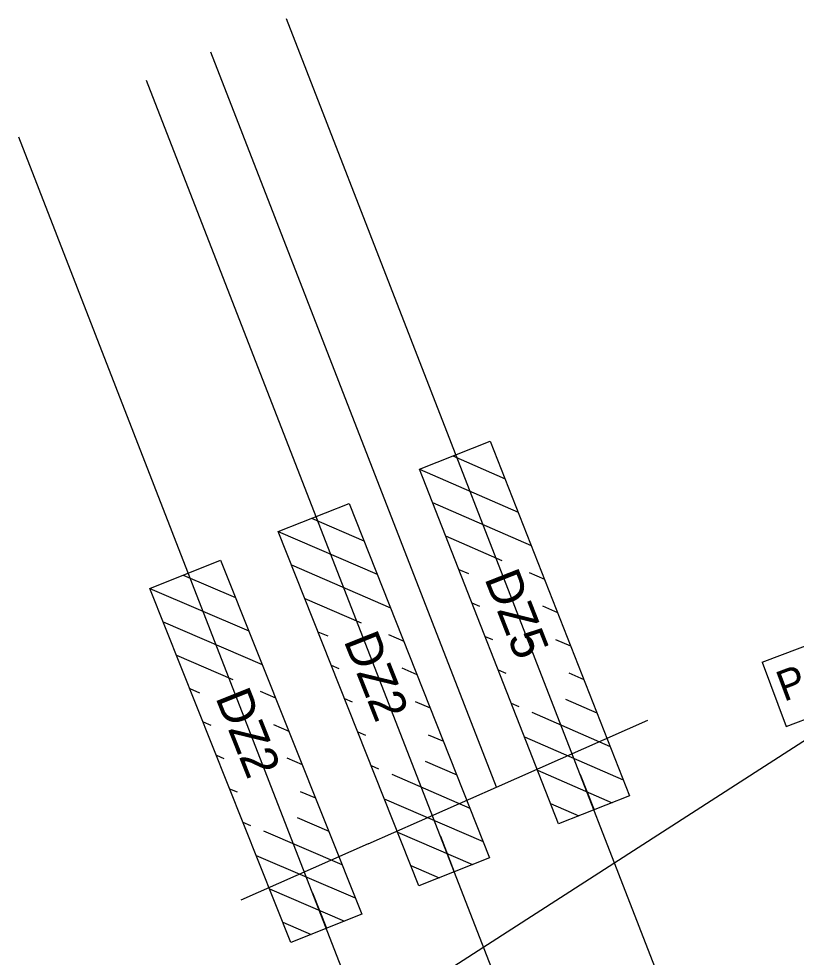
# Model space of a CAD drawing. Extents: x 510435 to 510719, y 1315254 to 1315553.
# Drawn here: x 510505.5 to 510566.7, y 1315479.2 to 1315553.1 of the extents above; entities that cross this region are included whole.
import ezdxf

# ---------------------------------------------------------------- set-up
doc = ezdxf.new("R2010")
doc.units = 0
for name, color, linetype in [('ConduitDB', 7, 'Continuous'), ('Default', 7, 'Continuous'), ('NonPlottingEle_dp', 7, 'Continuous'), ('OverheadStr', 7, 'Continuous'), ('PedHead', 7, 'Continuous')]:
    doc.layers.add(name, color=color, linetype=linetype)

# ---------------------------------------------------------------- blocks, each defined once
blk = doc.blocks.new('MastArmD4')
at = {"layer": 'OverheadStr'}
for p, q in [((0.25, 1.5), (0, 1.5)), ((0, 1.5), (0, -1.5)), ((0.25, 1.5), (0.25, -1.5)), ((0, -1.042), (0, 1.042)), ((0.25, 0.582), (11.7, 0.515)), ((9.7, 0.542), (46, 0.33)), ((9.7, 0.542), (9.7, -0.542)), ((11.7, 0.515), (11.7, -0.515)), ((46, 0.33), (46, -0.33)), ((0.25, -0.582), (11.7, -0.515)), ((9.7, -0.542), (46, -0.33)), ((0.25, -1.5), (0, -1.5))]:
    blk.add_line(p, q, dxfattribs=at)

msp = doc.modelspace()

# ---------------------------------------------------------------- linework, layer by layer
at = {"layer": 'ConduitDB'}
msp.add_line((510521.957, 1315467.05), (510573.336, 1315500.096), dxfattribs=at)
at = {"layer": 'Default'}
for p, q in [((510539.679, 1315518.645), (510543.79, 1315516.852)), ((510537.046, 1315517.611), (510544.824, 1315514.219)), ((510538.08, 1315514.979), (510545.857, 1315511.586)), ((510528.558, 1315513.735), (510532.677, 1315511.958)), ((510525.93, 1315512.691), (510533.721, 1315509.329)), ((510539.113, 1315512.346), (510543.543, 1315510.413)), ((510526.974, 1315510.062), (510534.765, 1315506.701)), ((510540.147, 1315509.713), (510540.91, 1315509.38)), ((510518.445, 1315509.267), (510522.566, 1315507.496)), ((510545.701, 1315509.472), (510546.891, 1315508.953)), ((510515.818, 1315508.219), (510523.614, 1315504.869)), ((510528.018, 1315507.433), (510532.455, 1315505.519)), ((510541.18, 1315507.08), (510541.779, 1315506.819)), ((510546.735, 1315506.839), (510547.924, 1315506.32)), ((510516.866, 1315505.592), (510524.662, 1315502.242)), ((510529.062, 1315504.805), (510529.826, 1315504.475)), ((510534.617, 1315504.586), (510535.809, 1315504.072)), ((510542.214, 1315504.447), (510542.813, 1315504.186)), ((510547.768, 1315504.206), (510548.958, 1315503.687)), ((510517.914, 1315502.965), (510522.354, 1315501.057)), ((510530.106, 1315502.176), (510530.706, 1315501.917)), ((510535.661, 1315501.957), (510536.853, 1315501.443)), ((510543.247, 1315501.814), (510543.846, 1315501.553)), ((510548.802, 1315501.574), (510549.991, 1315501.055)), ((510518.962, 1315500.338), (510519.727, 1315500.009)), ((510524.517, 1315500.128), (510525.71, 1315499.615)), ((510531.15, 1315499.547), (510531.75, 1315499.288)), ((510536.705, 1315499.329), (510537.897, 1315498.815)), ((510548.539, 1315499.506), (510551.025, 1315498.422)), ((510544.281, 1315499.182), (510544.88, 1315498.92)), ((510545.907, 1315498.472), (510552.058, 1315495.789)), ((510520.01, 1315497.71), (510520.611, 1315497.452)), ((510525.566, 1315497.5), (510526.758, 1315496.988)), ((510532.194, 1315496.919), (510532.794, 1315496.66)), ((510537.749, 1315496.7), (510538.941, 1315496.186)), ((510545.314, 1315496.549), (510553.092, 1315493.156)), ((510521.058, 1315495.083), (510521.659, 1315494.825)), ((510526.614, 1315494.873), (510527.806, 1315494.361)), ((510533.238, 1315494.29), (510533.838, 1315494.031)), ((510537.495, 1315494.631), (510539.985, 1315493.557)), ((510534.867, 1315493.587), (510541.029, 1315490.928)), ((510546.348, 1315493.916), (510552.235, 1315491.348)), ((510522.106, 1315492.456), (510522.707, 1315492.198)), ((510527.662, 1315492.246), (510528.854, 1315491.734)), ((510534.282, 1315491.661), (510542.073, 1315488.3)), ((510547.382, 1315491.283), (510549.602, 1315490.314)), ((510523.154, 1315489.829), (510523.755, 1315489.571)), ((510527.411, 1315490.177), (510529.903, 1315489.107)), ((510524.784, 1315489.129), (510530.951, 1315486.48)), ((510535.326, 1315489.033), (510541.224, 1315486.488)), ((510524.203, 1315487.202), (510531.999, 1315483.853)), ((510536.37, 1315486.404), (510538.595, 1315485.444)), ((510525.251, 1315484.575), (510531.152, 1315482.04)), ((510526.299, 1315481.948), (510528.525, 1315480.992))]:
    msp.add_line(p, q, dxfattribs=at)
for points in [[(510542.631, 1315519.804), (510553.593, 1315491.881), (510548.008, 1315489.688), (510537.046, 1315517.611)], [(510531.506, 1315514.906), (510542.579, 1315487.026), (510537.003, 1315484.812), (510525.93, 1315512.691)], [(510521.39, 1315510.442), (510532.506, 1315482.58), (510526.934, 1315480.357), (510515.818, 1315508.219)]]:
    msp.add_lwpolyline(points, close=True, dxfattribs=at)
at = {"layer": 'NonPlottingEle_dp'}
for p, q in [((510565.341, 1315453.401), (510526.579, 1315553.053)), ((510543.121, 1315492.582), (510520.623, 1315550.421)), ((510560.844, 1315431.795), (510515.57, 1315548.188)), ((510556.729, 1315412.031), (510505.499, 1315543.737)), ((510543.121, 1315492.582), (510555.033, 1315497.847)), ((510543.121, 1315492.582), (510555.033, 1315497.847)), ((510549.713, 1315493.58), (510550.8, 1315490.784)), ((510533.014, 1315488.116), (510543.121, 1315492.582)), ((510538.703, 1315488.715), (510539.791, 1315485.919)), ((510533.014, 1315488.116), (510522.98, 1315483.681)), ((510528.633, 1315484.264), (510529.358, 1315482.4)), ((510528.633, 1315484.264), (510529.72, 1315481.468))]:
    msp.add_line(p, q, dxfattribs=at)
at = {"layer": 'PedHead'}
for p, q in [((510564.038, 1315502.418), (510569.093, 1315504.316)), ((510564.038, 1315502.418), (510565.936, 1315497.362)), ((510565.936, 1315497.362), (510570.991, 1315499.261))]:
    msp.add_line(p, q, dxfattribs=at)

# ---------------------------------------------------------------- block references
at = {"layer": 'OverheadStr', "xscale": 1.0928961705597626, "yscale": 0.9999999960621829, "rotation": -108.57724603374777}
msp.add_blockref('MastArmD4', (510582.803, 1315495.741), dxfattribs=at)

# ---------------------------------------------------------------- texts
at = {"layer": 'Default'}
for s, rotation, p in [('DZ5 ', 291.43292, (510542.139, 1315509.014)), ('DZ2 ', 291.66166, (510531.057, 1315504.114)), ('DZ2 ', 291.75036, (510520.958, 1315499.65))]:
    msp.add_text(s, height=2.8001, rotation=rotation, dxfattribs=at).set_placement(p)
at = {"layer": 'PedHead'}
msp.add_text('P4', height=2.4, rotation=20.58198, dxfattribs=at).set_placement((510565.751, 1315499.28))

doc.saveas('drawing.dxf')
